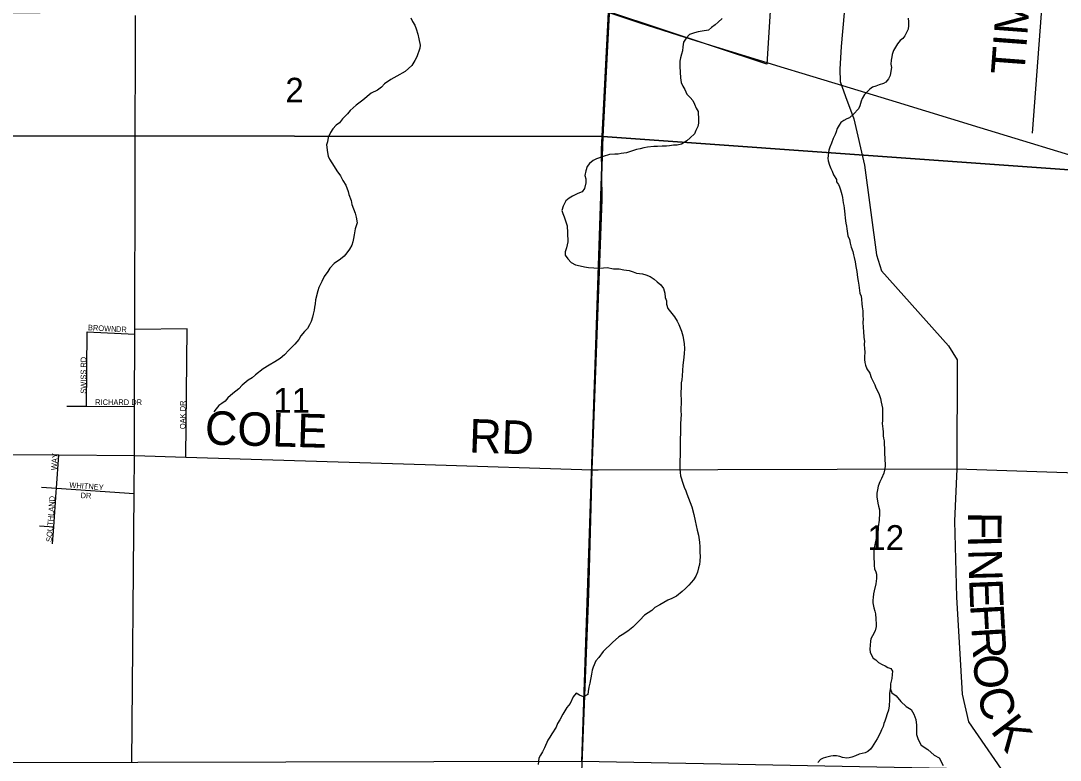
# Model space of a CAD drawing. Extents: x 1588073 to 2013523, y 1090242 to 1357120.
# Drawn here: x 1800917 to 1810221, y 1207738 to 1214356 of the extents above; entities that cross this region are included whole.
import ezdxf

# ---------------------------------------------------------------- set-up
doc = ezdxf.new("R2010")
doc.units = 0
for name, color, linetype in [('GM_X_Corporation', 7, 'Continuous'), ('GM_X_County_Road', 7, 'Continuous'), ('GM_X_County_Road_Text', 7, 'Continuous'), ('GM_X_Minor_River', 7, 'Continuous'), ('GM_X_Rail_Line', 7, 'Continuous'), ('GM_X_Section', 7, 'Continuous'), ('GM_X_Section_Text', 7, 'Continuous'), ('GM_X_Township_Road', 7, 'Continuous'), ('GM_X_Township_Road_Text', 7, 'Continuous'), ('GM_X_Township_Subdivision', 7, 'Continuous'), ('GM_X_Township_Subdivision_Text', 7, 'Continuous')]:
    doc.layers.add(name, color=color, linetype=linetype)

msp = doc.modelspace()

# ---------------------------------------------------------------- linework, layer by layer
at = {"layer": 'GM_X_Corporation'}
msp.add_lwpolyline([(1807627.4, 1214491.2), (1807595.4, 1213967.2), (1806179.7, 1214435.6)], dxfattribs=at)
at = {"layer": 'GM_X_County_Road'}
for points in [[(1808302.2, 1214597.8), (1808261.6, 1214126.4), (1808248.3, 1213924.1), (1808250.6, 1213813.7), (1808300.5, 1213677.8)], [(1806031.8, 1210335.5), (1806122.8, 1212756.7), (1806114, 1213206.1), (1806179.5, 1214432.2)], [(1808300.5, 1213677.8), (1808373.5, 1213478.8), (1808469.1, 1213064.1), (1808576.4, 1212260.2), (1808622.2, 1212117.1), (1809220.8, 1211445.7), (1809299, 1211322.1), (1809295.3, 1210345.4)], [(1805872.2, 1202410.7), (1805872.2, 1202410.7), (1805893.3, 1203721.9), (1805887.2, 1205464.7), (1805924, 1207252.9), (1806001.9, 1209227), (1806031.8, 1210335.5)], [(1809295.3, 1210345.4), (1809275.8, 1209878.5), (1809292.9, 1209198.4), (1809329.2, 1208588.1), (1809345.1, 1208329.2), (1809399.2, 1208081.6), (1810159.3, 1206984.5), (1810706.6, 1206492.4), (1811615.1, 1205771.9)]]:
    msp.add_lwpolyline(points, dxfattribs=at)
at = {"layer": 'GM_X_Minor_River'}
for points in [[(1804407.2, 1214381.9), (1804424.9, 1214349.7), (1804444.5, 1214317.4), (1804456.2, 1214283.2), (1804471.6, 1214234.9), (1804479.2, 1214194.8), (1804492.6, 1214138.5), (1804488.2, 1214110.5), (1804463.3, 1214032.6), (1804444.9, 1214000.7), (1804416.4, 1213954.9), (1804357.7, 1213903.4), (1804283.1, 1213860.1), (1804230.7, 1213830.6), (1804172.2, 1213791.2), (1804145.8, 1213761.4), (1804109.4, 1213735.7), (1804055.1, 1213708.2), (1803980.3, 1213646.9), (1803919.6, 1213599.5), (1803867, 1213553.9), (1803842.7, 1213524.1), (1803798.1, 1213478.5), (1803769.6, 1213442.7), (1803739.3, 1213421), (1803710.9, 1213389.2), (1803690.5, 1213357.4), (1803670, 1213311.5), (1803663.6, 1213273.5), (1803653.2, 1213245.6), (1803662.5, 1213177.3), (1803670.1, 1213145.2), (1803679.8, 1213117), (1803723.1, 1213052.4), (1803746.7, 1213014.1), (1803780.3, 1212969.6), (1803799.8, 1212927.3), (1803825.4, 1212885), (1803848.8, 1212828.6), (1803854.5, 1212800.5), (1803875.9, 1212748.1), (1803881.5, 1212712), (1803910.6, 1212635.5), (1803920.3, 1212599.4), (1803929.7, 1212547.1), (1803911, 1212493.2), (1803900.4, 1212441.2), (1803896, 1212407.2)], [(1807195.1, 1214376.2), (1807160.7, 1214344.5), (1807132.4, 1214320.8), (1807100.1, 1214295.1), (1807071.8, 1214273.3), (1807017.6, 1214261.9), (1806979.5, 1214256.3), (1806949.3, 1214248.6), (1806903.1, 1214233), (1806874.7, 1214201.3), (1806850.3, 1214165.4), (1806843.8, 1214123.4), (1806839.4, 1214087.4), (1806831, 1214057.4), (1806822.6, 1214023.4), (1806816.3, 1213995.5), (1806817.7, 1213947.3), (1806822.6, 1213845.1), (1806828.1, 1213802.9), (1806843.8, 1213770.7), (1806861.5, 1213742.4), (1806879, 1213700.2), (1806908.7, 1213669.8), (1806932.4, 1213641.5), (1806948.1, 1213609.2), (1806963.7, 1213575), (1806981.4, 1213542.7), (1806984.5, 1213470.6), (1806982.2, 1213440.5), (1806977.8, 1213410.5), (1806959.4, 1213372.6), (1806947.1, 1213344.7), (1806908.6, 1213309), (1806878.2, 1213281.3), (1806831.8, 1213251.7), (1806793.7, 1213244.1), (1806759.6, 1213242.5), (1806725.5, 1213236.8), (1806697.5, 1213235.1), (1806657.4, 1213233.5), (1806617.3, 1213230), (1806585.2, 1213230.3), (1806527.1, 1213224.9), (1806495, 1213219.2), (1806460.8, 1213209.6), (1806428.7, 1213203.9), (1806382.5, 1213190.4), (1806340.3, 1213174.8), (1806292.1, 1213167.3), (1806264, 1213163.6), (1806236, 1213161.9), (1806187.9, 1213158.4), (1806131.6, 1213140.9), (1806069.3, 1213121.6), (1806041, 1213105.8), (1806008.7, 1213080.1), (1805986.3, 1213050.3), (1805973.9, 1213014.4), (1805967.4, 1212970.3), (1805975.1, 1212942.2), (1805974.7, 1212904.1), (1805962.1, 1212856.2), (1805941.7, 1212824.3), (1805903.5, 1212810.7), (1805857.1, 1212785.1), (1805826.9, 1212769.4), (1805796.6, 1212745.7), (1805772, 1212695.8), (1805759.5, 1212657.9), (1805769.2, 1212629.7), (1805780.9, 1212601.6), (1805796.5, 1212557.3), (1805808.1, 1212521.1), (1805811.3, 1212456.9), (1805814.4, 1212378.7), (1805801.8, 1212324.8), (1805791.4, 1212288.8), (1805791, 1212256.7)], [(1808859.6, 1214378.5), (1808863.2, 1214346.4), (1808862.8, 1214314.3), (1808860.5, 1214282.3), (1808846.1, 1214250.4), (1808829.7, 1214222.5), (1808811.4, 1214196.6), (1808789.2, 1214178.8), (1808764.8, 1214151), (1808746.4, 1214119.1), (1808730.1, 1214091.3), (1808717.7, 1214055.3), (1808713.4, 1214033.3), (1808707.1, 1214003.3), (1808706.7, 1213967.2), (1808710.3, 1213939.2), (1808706, 1213905.1), (1808699.5, 1213867.1), (1808685.1, 1213835.2), (1808660.7, 1213805.4), (1808638.6, 1213793.6), (1808600.4, 1213782), (1808570.2, 1213770.3), (1808540.1, 1213760.6), (1808515.9, 1213744.8), (1808497.6, 1213723), (1808469.2, 1213695.2), (1808448.8, 1213659.3), (1808440.5, 1213635.4), (1808428, 1213593.4), (1808415.7, 1213567.5), (1808371.1, 1213519.9), (1808334.7, 1213488.2), (1808310.5, 1213478.4), (1808284.3, 1213464.7), (1808258.1, 1213446.9), (1808243.8, 1213421), (1808225.4, 1213391.2), (1808215.1, 1213363.2), (1808206.8, 1213337.2), (1808188.4, 1213303.4), (1808173.9, 1213261.4), (1808159.4, 1213223.5), (1808151.1, 1213197.6), (1808146.8, 1213175.6), (1808144.5, 1213147.5), (1808142.3, 1213125.5), (1808144, 1213103.4), (1808155.6, 1213065.2), (1808167.3, 1213033), (1808179, 1213010.9), (1808190.6, 1212976.7), (1808218.2, 1212936.3), (1808220, 1212914.2), (1808235.7, 1212892), (1808245.5, 1212869.9), (1808253.2, 1212843.7), (1808266.8, 1212801.5), (1808272.5, 1212775.4), (1808276.2, 1212749.3), (1808279.9, 1212725.2), (1808283.7, 1212703.1), (1808287.4, 1212679), (1808291.1, 1212650.9), (1808294.8, 1212624.8), (1808296.4, 1212588.7), (1808303.9, 1212544.6), (1808307.6, 1212518.5), (1808311.3, 1212494.4), (1808320.6, 1212432.1), (1808334.3, 1212397.9), (1808339.9, 1212365.8), (1808351.5, 1212329.6), (1808365.1, 1212291.4), (1808370.8, 1212261.2), (1808376.5, 1212237.1), (1808386.1, 1212199), (1808391.6, 1212156.8), (1808401.1, 1212112.6), (1808406.5, 1212058.4), (1808412.1, 1212026.3), (1808419.7, 1211988.2), (1808428.9, 1211917.9), (1808438.6, 1211889.8), (1808442.4, 1211865.7), (1808445.9, 1211823.5), (1808449.6, 1211795.4), (1808453.2, 1211761.3), (1808454.7, 1211717.2), (1808456.3, 1211683.1)], [(1803896, 1212407.2), (1803889.7, 1212377.2), (1803879.3, 1212347.3), (1803858.9, 1212311.4), (1803834.5, 1212279.6), (1803812.1, 1212249.8), (1803777.8, 1212222.1), (1803723.2, 1212182.6), (1803684.7, 1212140.9), (1803666.3, 1212111.1), (1803633.8, 1212067.3), (1803613.2, 1212021.4), (1803584.6, 1211967.6), (1803576.2, 1211937.6), (1803555.3, 1211859.7), (1803550.9, 1211823.7), (1803546.6, 1211793.7), (1803544.2, 1211765.6), (1803535.8, 1211731.6), (1803529.5, 1211703.7), (1803515.1, 1211665.7), (1803502.7, 1211635.8), (1803484.3, 1211601.9), (1803456, 1211576.2), (1803423.5, 1211536.4), (1803405, 1211502.6), (1803370.5, 1211460.8), (1803315.9, 1211409.3), (1803279.3, 1211367.6), (1803238.9, 1211334), (1803192.5, 1211302.4), (1803142.1, 1211274.9), (1803087.6, 1211239.4), (1803016.9, 1211186.1), (1802988.5, 1211160.3), (1802952.3, 1211140.6), (1802897.7, 1211095.1), (1802869.2, 1211061.4), (1802814.7, 1211019.9), (1802770.2, 1210980.3), (1802745.8, 1210952.5), (1802717.5, 1210930.7), (1802689.3, 1210913), (1802666.9, 1210883.2), (1802646.6, 1210855.3)], [(1805791, 1212256.7), (1805814.7, 1212226.4), (1805844.4, 1212194), (1805882.2, 1212171.6), (1805924.2, 1212163.1), (1805964.1, 1212154.7), (1805998.1, 1212148.3), (1806046.1, 1212143.8), (1806082.1, 1212141.4), (1806134.2, 1212144.8), (1806166.3, 1212148.5), (1806222.3, 1212135.9), (1806274.3, 1212135.3), (1806314.3, 1212126.9), (1806364.3, 1212120.3), (1806398.2, 1212107.9), (1806430.1, 1212097.6), (1806482.1, 1212091), (1806512.1, 1212082.7), (1806552, 1212068.2), (1806585.7, 1212043.8), (1806613.5, 1212019.5), (1806645.2, 1211993.1), (1806670.9, 1211958.7), (1806682.4, 1211918.5), (1806686, 1211880.4), (1806695.7, 1211848.2), (1806697.3, 1211820.2), (1806708.9, 1211782), (1806744.4, 1211735.5), (1806770.2, 1211707.2), (1806791.8, 1211668.8), (1806807.4, 1211638.6), (1806830.8, 1211578.2), (1806842.3, 1211536), (1806849.9, 1211501.9), (1806855.5, 1211463.8), (1806859.1, 1211423.6), (1806856.5, 1211373.6), (1806847.9, 1211319.5), (1806843.3, 1211273.5), (1806836.2, 1211177.4), (1806833.8, 1211143.3), (1806829.5, 1211115.3), (1806829.2, 1211085.2), (1806826.4, 1211017.1), (1806827.7, 1210957), (1806826.6, 1210860.8), (1806828.3, 1210830.7), (1806823.4, 1210752.6), (1806822.4, 1210672.5), (1806819.7, 1210606.4), (1806819.3, 1210574.3), (1806820.5, 1210500.1), (1806820, 1210460.1), (1806817.6, 1210426), (1806816.7, 1210345.9), (1806818.3, 1210311.8), (1806822, 1210281.7), (1806845.2, 1210209.3), (1806854.9, 1210181.1), (1806870.5, 1210148.9), (1806880.2, 1210120.7), (1806909.4, 1210044.3), (1806923, 1210006.1), (1806942.2, 1209935.7), (1806953.6, 1209881.5), (1806972.7, 1209797.1), (1806984.2, 1209752.9), (1806993.5, 1209688.7), (1806995, 1209648.6), (1806996.4, 1209598.4), (1806998.1, 1209564.4), (1806995.5, 1209518.3), (1806993.2, 1209488.3), (1806984.8, 1209458.3), (1806974.4, 1209420.3), (1806960, 1209384.4), (1806937.6, 1209352.6), (1806897, 1209304.9), (1806866.6, 1209275.2), (1806836.2, 1209247.4), (1806785.7, 1209205.9), (1806745.4, 1209186.3), (1806709.2, 1209170.6), (1806672.9, 1209149), (1806638.6, 1209127.3), (1806592.3, 1209105.8), (1806565.9, 1209078), (1806499.3, 1209034.6), (1806458.8, 1208991), (1806396, 1208929.5), (1806351.5, 1208893.9), (1806301, 1208860.4), (1806270.8, 1208840.7), (1806214.1, 1208791.2), (1806131.1, 1208709.9), (1806092.4, 1208656.2), (1806066.1, 1208628.4), (1806041.4, 1208570.6), (1806031, 1208542.6)], [(1808456.3, 1211683.1), (1808456, 1211661.1), (1808457.4, 1211607), (1808461.1, 1211576.9), (1808462.5, 1211522.7), (1808468.1, 1211488.6), (1808467.8, 1211460.6), (1808469.3, 1211420.4), (1808471, 1211392.4), (1808470.5, 1211346.3), (1808470.2, 1211324.2), (1808473.9, 1211296.1), (1808479.7, 1211274), (1808491.3, 1211239.8), (1808516.9, 1211201.5), (1808530.5, 1211163.3), (1808561.8, 1211098.8), (1808571.5, 1211070.6), (1808585.2, 1211044.4), (1808600.8, 1211010.2), (1808612.5, 1210976), (1808618.1, 1210943.9), (1808625.8, 1210915.8), (1808631.5, 1210887.6), (1808630.2, 1210777.4), (1808627.9, 1210751.4), (1808633.4, 1210705.2), (1808635.1, 1210677.2), (1808636.7, 1210641.1), (1808638.4, 1210619), (1808644.2, 1210596.9), (1808645.8, 1210564.8), (1808647.4, 1210530.7), (1808648.8, 1210476.6), (1808650.5, 1210444.5), (1808650.2, 1210418.5), (1808653.9, 1210396.4), (1808653.6, 1210372.3), (1808651.3, 1210346.3), (1808642.9, 1210308.3), (1808622.3, 1210258.4), (1808607.9, 1210228.5), (1808591.5, 1210190.6), (1808585.1, 1210156.6), (1808578.7, 1210126.6), (1808580.4, 1210096.6), (1808589.7, 1210038.3), (1808593.4, 1210012.2), (1808603.1, 1209978.1), (1808602.7, 1209948), (1808600, 1209885.9), (1808593.3, 1209825.9), (1808591, 1209795.8), (1808578.4, 1209743.9), (1808571.9, 1209707.9), (1808565.6, 1209679.9), (1808555.1, 1209637.9), (1808552.9, 1209615.9), (1808554.4, 1209571.8), (1808554.1, 1209549.7), (1808555.6, 1209505.6), (1808555.3, 1209479.6), (1808559, 1209449.5), (1808570.7, 1209425.3), (1808576.5, 1209403.2), (1808578, 1209363.1), (1808571.5, 1209317.1), (1808554.7, 1209253.1), (1808550.4, 1209227.1), (1808548.1, 1209195.1), (1808543.8, 1209169.1), (1808545.5, 1209145), (1808553, 1209102.8), (1808562.7, 1209072.7), (1808568.4, 1209046.6), (1808571.9, 1209004.4), (1808575.4, 1208956.3), (1808573.1, 1208934.3), (1808564.7, 1208896.3), (1808540.1, 1208850.5), (1808525.8, 1208824.6), (1808523.5, 1208802.6), (1808519.1, 1208766.5), (1808516.7, 1208730.5), (1808520.4, 1208706.4), (1808532.1, 1208678.2), (1808547.9, 1208652), (1808569.7, 1208635.7), (1808593.5, 1208613.4), (1808627.3, 1208595), (1808655.2, 1208582.7), (1808677.1, 1208568.4), (1808705, 1208560.1), (1808720.8, 1208535.9), (1808716.4, 1208503.9), (1808714, 1208469.8), (1808703.5, 1208421.9), (1808701.1, 1208387.8), (1808694.5, 1208337.8), (1808692.2, 1208309.8), (1808691.8, 1208279.7)], [(1806031, 1208542.6), (1806024.6, 1208506.6), (1806009.7, 1208426.6), (1806003.3, 1208392.6), (1805996.8, 1208352.6), (1805994.5, 1208324.6), (1805954.2, 1208305), (1805918.4, 1208321.4), (1805888.5, 1208337.8), (1805862.1, 1208306), (1805833.4, 1208246.1), (1805804.9, 1208210.4), (1805770.2, 1208150.6), (1805741.6, 1208098.8), (1805721.2, 1208067), (1805710.8, 1208033), (1805670, 1207973.3), (1805653.7, 1207945.5), (1805635.3, 1207917.6), (1805606.5, 1207849.8), (1805588.1, 1207811.9), (1805569.7, 1207784.1), (1805553.4, 1207756.2), (1805548.7, 1207700.1)], [(1808700.4, 1208382.4), (1808714.6, 1208341.6), (1808752.3, 1208315.1), (1808793.8, 1208262.6), (1808843.4, 1208220), (1808887.1, 1208191.4), (1808910.6, 1208149.1), (1808930.1, 1208100.8), (1808935.6, 1208050.6), (1808934.6, 1207968.5), (1808950.1, 1207922.2), (1808977.6, 1207873.8), (1809035.2, 1207833.1), (1809092.7, 1207784.4), (1809136.5, 1207757.9), (1809173.8, 1207689.4)], [(1808691.8, 1208279.7), (1808689.2, 1208225.6), (1808684.7, 1208185.6), (1808672.3, 1208151.6), (1808661.9, 1208113.7), (1808651.6, 1208087.8), (1808641.3, 1208065.8), (1808637, 1208039.8), (1808622.6, 1208009.9), (1808608.3, 1207980), (1808581.7, 1207928.2), (1808553.1, 1207880.4), (1808536.8, 1207858.5), (1808522.5, 1207836.6), (1808498.3, 1207816.8), (1808476.1, 1207805.1), (1808448, 1207799.3), (1808421.9, 1207791.6), (1808389.6, 1207775.9), (1808355.5, 1207764.3), (1808333.4, 1207758.5), (1808311.3, 1207756.7), (1808273.3, 1207763.1), (1808247.4, 1207771.4), (1808217.4, 1207775.8), (1808189.4, 1207776.1), (1808167.3, 1207774.3), (1808145.2, 1207768.5), (1808121.1, 1207762.8), (1808099, 1207755), (1808074.8, 1207743.2), (1808050.5, 1207717.4)]]:
    msp.add_lwpolyline(points, dxfattribs=at)
at = {"layer": 'GM_X_Rail_Line'}
msp.add_lwpolyline([(1806190.6, 1214426.9), (1806458.6, 1214336.8), (1806860.5, 1214208.7), (1807137.7, 1214123.7), (1807749.3, 1213935.7), (1807908.5, 1213887.2), (1808271.2, 1213776.1), (1808752.6, 1213629.4), (1809502.5, 1213401.4), (1810580, 1213071.4)], dxfattribs=at)
at = {"layer": 'GM_X_Section'}
for points in [[(1806367.2, 1217950.4), (1806128.5, 1213321.2), (1800603.4, 1213325.3), (1800604.2, 1214425.9), (1805429.1, 1214456.2), (1805464.7, 1217967.9)], [(1806367.2, 1217950.4), (1806815.3, 1217935.6), (1812121.6, 1217818.8), (1811932.1, 1213063.2), (1811927.2, 1212905.2), (1806128.5, 1213321.2)], [(1806128.5, 1213321.2), (1805939.8, 1207725.3), (1800636.8, 1207714), (1800603.4, 1213325.3)], [(1811927.2, 1212905.2), (1811697.1, 1207745.7), (1811690.3, 1207615.7), (1805939.8, 1207725.3), (1806128.5, 1213321.2)]]:
    msp.add_lwpolyline(points, close=True, dxfattribs=at)
at = {"layer": 'GM_X_Township_Road'}
for points in [[(1809973.1, 1213351), (1810190, 1216249.6)], [(1801934.6, 1210465.2), (1801934.6, 1210465.2), (1801935.7, 1210904.4), (1801937.4, 1211550.2), (1801937.5, 1211592.1), (1801941.1, 1212989.4), (1801944.8, 1214404.4)], [(1795379, 1210300.3), (1795773, 1210311.1), (1795801.4, 1210311.9), (1796027.3, 1210318.1), (1796438.9, 1210329.4), (1797360.4, 1210354.7), (1797906.7, 1210372.5), (1798030.5, 1210379.2), (1798670.3, 1210413.9), (1799034, 1210433.6), (1799202, 1210442.7), (1799559, 1210457), (1800112.1, 1210471.8), (1800365.1, 1210474.2), (1801257.1, 1210470.6), (1801934.6, 1210465.2)], [(1801912.3, 1207714.2), (1801931.8, 1210125), (1801934.6, 1210465.2)], [(1801934.6, 1210465.2), (1802395.3, 1210450.7), (1804537.1, 1210383.5), (1806031.8, 1210335.5)], [(1806031.8, 1210335.5), (1806084.4, 1210335.7)], [(1806084.4, 1210335.7), (1809295.3, 1210345.4)], [(1809295.3, 1210345.4), (1811805.7, 1210261.1)]]:
    msp.add_lwpolyline(points, dxfattribs=at)
at = {"layer": 'GM_X_Township_Subdivision'}
for points in [[(1801506.8, 1210907), (1801511.3, 1211570.9)], [(1801511.3, 1211570.9), (1801937.4, 1211550.2)], [(1802395.3, 1210450.7), (1802405.8, 1211598.8), (1801937.5, 1211592.1)], [(1801330.3, 1210908), (1801506.8, 1210907), (1801935.7, 1210904.4)], [(1801201.5, 1209674.6), (1801212.1, 1209827.2), (1801233.8, 1210136.5), (1801236.4, 1210173.7), (1801257.1, 1210470.6)], [(1801103.6, 1210182.9), (1801236.4, 1210173.7), (1801931.8, 1210125)], [(1801083.4, 1209836.2), (1801212.1, 1209827.2)]]:
    msp.add_lwpolyline(points, dxfattribs=at)

# ---------------------------------------------------------------- texts
at = {"layer": 'GM_X_County_Road_Text'}
for s, rotation, p in [('F', 269.78143, (1809396.2, 1209961.5)), ('I', 271.40967, (1809395.5, 1209749.8)), ('N', 271.52404, (1809398.6, 1209626)), ('E', 272.3129, (1809405.7, 1209357.6)), ('F', 273.20266, (1809415, 1209128.3)), ('R', 273.47658, (1809426.5, 1208924.7)), ('O', 273.94348, (1809441.6, 1208676)), ('C', 285.5303, (1809470.9, 1208347.5)), ('K', 306.94604, (1809590.7, 1208000.9))]:
    msp.add_text(s, height=300, rotation=rotation, dxfattribs=at).set_placement(p)
at = {"layer": 'GM_X_Section_Text'}
for s, p in [('2', (1803285.6, 1213624.6)), ('11', (1803177.8, 1210848.7)), ('12', (1808495.2, 1209620.6))]:
    msp.add_text(s, height=221, rotation=0.00001, dxfattribs=at).set_placement(p)
at = {"layer": 'GM_X_Township_Road_Text'}
for s, rotation, p in [('TIMPE', 85.63713, (1809899.3, 1213864.5)), ('COLE', 358.4233, (1802562.9, 1210563.8)), ('RD', 358.02523, (1804926.5, 1210493.3))]:
    msp.add_text(s, height=300, rotation=rotation, dxfattribs=at).set_placement(p)
at = {"layer": 'GM_X_Township_Subdivision_Text'}
for s, rotation, p in [('BROWN', 356.69797, (1801517.4, 1211586)), ('DR', 356.98842, (1801768.1, 1211572.8)), ('SWISS RD', 90, (1801503, 1211017.8)), ('RICHARD DR', 0.00001, (1801582.8, 1210917.2)), ('OAK DR', 90, (1802391.8, 1210701)), ('WAY', 86.42578, (1801239, 1210332)), ('WHITNEY', 355.60027, (1801350.3, 1210178)), ('SOUTHLAND', 85.96198, (1801195, 1209689.7)), ('DR', 356.98902, (1801451.2, 1210084.2))]:
    msp.add_text(s, height=50, rotation=rotation, dxfattribs=at).set_placement(p)

doc.saveas('drawing.dxf')
